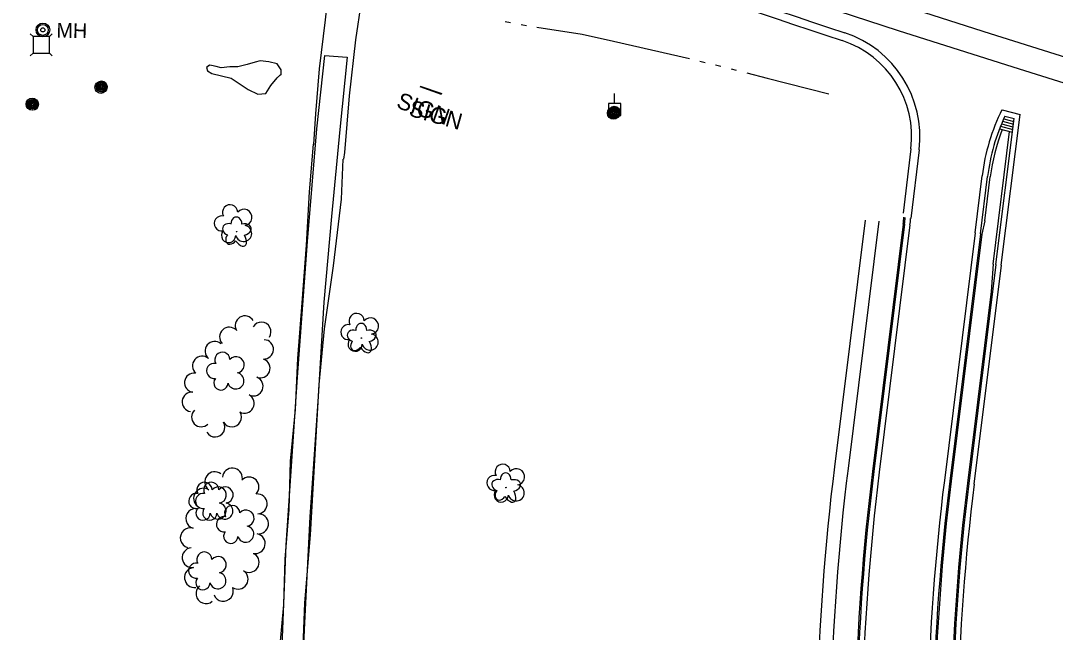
# Model space of a CAD drawing. Extents: x 588843 to 2552415, y 180129 to 269402.
# Drawn here: x 596189.9 to 596568.3, y 184162.7 to 184386.4 of the extents above; entities that cross this region are included whole.
import ezdxf

# ---------------------------------------------------------------- set-up
doc = ezdxf.new("R2010")
doc.units = 0
for name, color, linetype in [('C-ROAD-CURB-BACK-N-STH20-2', 7, 'Continuous'), ('C-ROAD-CURB-FACE-N-STH20-2', 7, 'Continuous'), ('C-ROAD-CURB-FLANGE-N-STH20-2', 7, 'Continuous'), ('Default', 7, 'Continuous'), ('E_DWY', 7, 'Continuous'), ('E_LAND_TreeLine_P', 7, 'Continuous'), ('E_LAND_Vegetation', 7, 'Continuous'), ('E_MISCPROP', 7, 'Continuous'), ('E_RDWY', 7, 'Continuous'), ('E_RDWY_Gravel', 7, 'Continuous'), ('E_SGN', 7, 'Continuous'), ('E_SGN_Text', 7, 'Continuous'), ('E_UTL_EPowerPole', 7, 'Continuous'), ('E_UTL_MH', 7, 'Continuous'), ('E_UTL_SAN', 7, 'Continuous'), ('E_WTR_P', 7, 'Continuous'), ('Level 14', 7, 'Continuous'), ('Level 17', 7, 'Continuous'), ('Level 18', 7, 'Continuous'), ('Level 19', 7, 'Continuous'), ('Level 21', 7, 'Continuous')]:
    doc.layers.add(name, color=color, linetype=linetype)

# ---------------------------------------------------------------- blocks, each defined once
blk = doc.blocks.new('POLE')
at = {"layer": 'Default'}
for radius in [4.46, 3.35, 2.23, 1.12]:
    blk.add_circle((0, 0), radius, dxfattribs=at)
blk = doc.blocks.new('SIGN')
at = {"layer": 'Default'}
blk.add_text('SIGN', height=12, dxfattribs=at).set_placement((-18.55, -6))
blk = doc.blocks.new('MH')
at = {"layer": 'E_UTL_MH'}
for radius in [5, 4, 1.5]:
    blk.add_circle((0, 0), radius, dxfattribs=at)
blk.add_text('MH', height=10.8, dxfattribs=at).set_placement((10, -5.4))
blk = doc.blocks.new('SIGN_3')
at = {"layer": 'E_SGN'}
blk.add_text('SIGN', height=39.37, dxfattribs=at).set_placement((-56.1, -19.7))
blk = doc.blocks.new('POLE_3')
at = {"layer": 'E_MISCPROP'}
for radius in [14.6, 11, 7.32, 3.66]:
    blk.add_circle((0, 0), radius, dxfattribs=at)
blk = doc.blocks.new('DTRE_4')
at = {"layer": 'E_LAND_Vegetation'}
blk.add_circle((-0.6, 0), 0.601, dxfattribs=at)
for centre, major_axis, ratio in [((-6.1, 17.5), (4.5, -16.3), 0.782863), ((13.3, 9), (-17.3, -9.6), 0.691916), ((-19.3, 0.5), (16.2, -0.4), 0.832022), ((-8.2, -17.2), (5.9, 15.9), 0.716896), ((11.6, -12.2), (-16.4, 15), 0.560249)]:
    blk.add_ellipse(centre, major_axis=major_axis, ratio=ratio, start_param=1.570796, end_param=4.712389, dxfattribs=at)

msp = doc.modelspace()

# ---------------------------------------------------------------- linework, layer by layer
at = {"layer": 'C-ROAD-CURB-BACK-N-STH20-2'}
for p, q in [((596545.58, 184297.28), (596551.62, 184345.8)), ((596547.91, 184346.8), (596552.59, 184345.54)), ((596542.52, 184313.17), (596544.53, 184329.3)), ((596542.52, 184313.17), (596541.45, 184308.29))]:
    msp.add_line(p, q, dxfattribs=at)
msp.add_arc((596615.97, 184320.41), 72, 158.7204, 172.9059, dxfattribs=at)
at = {"layer": 'C-ROAD-CURB-FACE-N-STH20-2'}
for p, q in [((596546.57, 184297.15), (596553.22, 184350.55)), ((596549.06, 184349.6), (596552.97, 184348.55)), ((596549.48, 184350.52), (596553.09, 184349.55)), ((596549.9, 184351.44), (596553.22, 184350.55)), ((596548.28, 184347.74), (596552.72, 184346.54)), ((596548.67, 184348.67), (596552.84, 184347.54)), ((596540.96, 184308.4), (596543.53, 184329.42))]:
    msp.add_line(p, q, dxfattribs=at)
msp.add_arc((596615.97, 184320.41), 73, 154.8409, 172.9059, dxfattribs=at)
at = {"layer": 'C-ROAD-CURB-FLANGE-N-STH20-2'}
for p, q in [((596548.82, 184353.81), (596555.42, 184352.03)), ((596548.56, 184296.91), (596555.42, 184352.03)), ((596539, 184308.83), (596541.55, 184329.67))]:
    msp.add_line(p, q, dxfattribs=at)
msp.add_arc((596615.97, 184320.41), 75, 153.5579, 172.9059, dxfattribs=at)
at = {"layer": 'E_DWY'}
for points in [[(596290.97, 184460.54), (596295.53, 184454.25), (596299.41, 184447.58), (596301.75, 184439.79), (596303.47, 184432.76), (596304.56, 184425.1), (596304.14, 184416.8), (596302.91, 184401.69), (596301.19, 184386.71), (596299.06, 184368.73), (596297.69, 184352.26), (596296.95, 184341.16)], [(596353.91, 184437.27), (596348.43, 184436.95), (596342.49, 184435.95), (596337.19, 184434.41), (596331.48, 184430.97), (596328.08, 184428.43), (596324.89, 184425.61), (596321.42, 184421.31), (596319.34, 184417.39), (596317.74, 184413.72), (596316.45, 184407.31), (596312.33, 184379.36), (596309.97, 184358.92), (596308.29, 184338.18), (596307.96, 184335.69)], [(596301.04, 184373.66), (596298.11, 184346.87), (596294.61, 184305.58), (596291.04, 184256.01), (596286.9, 184194.55), (596284.63, 184139.31), (596281.58, 184091.57), (596279.28, 184055.66)], [(596309.26, 184372.99), (596306.64, 184346.52), (596303.55, 184314.78), (596300.77, 184283.37), (596298.7, 184248.96), (596295.66, 184204.95), (596293.69, 184166.14), (596292.11, 184132), (596292.06, 184096.28), (596292.01, 184056.2)], [(596301.04, 184373.64), (596309.26, 184372.99)], [(596296.95, 184341.16), (596296.94, 184340.91)]]:
    msp.add_lwpolyline(points, dxfattribs=at)
at = {"layer": 'E_LAND_TreeLine_P'}
for centre, radius, start, end in [((596271.87, 184274.85), 3.54, 30.6326, 210.6326), ((596266.16, 184270.72), 3.54, 42.9001, 222.9001), ((596277.88, 184272.56), 3.54, 327.7743, 147.7743), ((596260.83, 184265.53), 3.54, 49.7198, 229.7198), ((596278.8, 184266.15), 3.54, 267.0712, 87.0712), ((596256.25, 184260.12), 3.54, 49.7198, 229.7198), ((596277.55, 184259.26), 3.54, 248.9694, 68.9694), ((596253.34, 184253.97), 3.54, 82.6946, 262.6946), ((596275, 184252.65), 3.54, 248.9694, 68.9694), ((596252.44, 184246.94), 3.54, 82.6946, 262.6946), ((596271.72, 184246.37), 3.54, 241.2564, 61.2564), ((596255.9, 184241.38), 3.54, 134.4189, 314.4189), ((596267.09, 184241.33), 3.54, 211.2849, 31.2849), ((596261.03, 184237.65), 3.54, 211.2849, 31.2849), ((596260.85, 184217.73), 3.66, 52.9133, 232.9133), ((596267.3, 184219.07), 3.66, 355.4737, 175.4737), ((596273.36, 184215.78), 3.66, 315.1092, 135.1092), ((596256.78, 184211.68), 3.66, 65.7368, 245.7368), ((596276.36, 184209.61), 3.66, 273.8176, 93.8176), ((596253.92, 184204.29), 3.66, 74.1638, 254.1638), ((596276.84, 184202.3), 3.66, 273.8176, 93.8176), ((596251.92, 184197.24), 3.66, 74.1638, 254.1638), ((596275.65, 184195.1), 3.66, 258.178, 78.178), ((596252.61, 184189.98), 3.66, 96.6673, 276.6673), ((596273.42, 184188.23), 3.66, 236.5512, 56.5512), ((596253.46, 184182.7), 3.66, 96.6673, 276.6673), ((596269.38, 184182.12), 3.66, 236.5512, 56.5512), ((596257.65, 184176.83), 3.66, 129.2885, 309.2885), ((596264, 184177.68), 3.66, 201.2807, 21.2807)]:
    msp.add_arc(centre, radius, start, end, dxfattribs=at)
at = {"layer": 'E_RDWY'}
for points in [[(595944.91, 184608.43), (595961.18, 184603.08), (595975.38, 184597.49), (596005.04, 184584.51), (596046.53, 184566.71), (596092.38, 184547.47), (596140.6, 184527.77), (596188.57, 184508.66), (596236, 184490.22), (596283.28, 184472.34), (596335.36, 184453.1), (596389, 184433.84), (596442.9, 184415.12), (596490.31, 184399.18), (596544.44, 184381.64), (596596.04, 184365.45), (596657.88, 184346.56), (596699.92, 184334.01), (596744.2, 184321.66), (596790.46, 184308.95), (596813.68, 184302.57)], [(596515.5, 184339.48), (596512.63, 184316.01)], [(596518.48, 184339.12), (596515.41, 184314.08)], [(596498.75, 184313.41), (596487.54, 184223.23)], [(596503.75, 184313.08), (596492.51, 184222.62)], [(596512.68, 184311.97), (596501.44, 184221.51)], [(596513.18, 184311.91), (596501.93, 184221.45)], [(596515.16, 184311.66), (596503.92, 184221.2)], [(596539, 184308.83), (596527.74, 184218.24)], [(596540.96, 184308.4), (596529.72, 184217.99)], [(596541.45, 184308.29), (596530.22, 184217.93)], [(596545.58, 184297.28), (596544.88, 184287.29), (596536.17, 184217.19)], [(596546.61, 184297.15), (596536.67, 184217.13)], [(596538.65, 184216.88), (596548.6, 184296.9)]]:
    msp.add_lwpolyline(points, dxfattribs=at)
for centre, radius, start, end in [((598307.84, 189884.49), 5794.62, 249.753018, 251.730667), ((598307.84, 189884.49), 5797.62, 249.75172, 251.730667), ((596478.78, 184343.98), 40, 353.0262, 71.7307), ((596478.78, 184343.98), 37, 353.0262, 71.7307), ((596455.62, 184319.06), 57.5, 352.9143, 355.4734), ((596455.62, 184319.06), 58, 352.9143, 355.4056), ((596455.62, 184319.06), 60, 352.9143, 355.1459), ((597340.98, 184117.15), 860, 172.91432, 184.56653), ((597340.98, 184117.15), 855, 172.91432, 184.56653), ((597340.98, 184117.15), 846, 172.91432, 184.56653), ((597340.98, 184117.15), 845.5, 172.91432, 184.56653), ((597340.98, 184117.15), 843.5, 172.91432, 184.56653), ((597340.98, 184117.15), 819.5, 172.91432, 184.56653), ((597340.98, 184117.15), 817.5, 172.91432, 184.56653), ((597340.98, 184117.15), 817, 172.91432, 184.56653), ((597340.98, 184117.15), 811, 172.91432, 184.56653), ((597340.98, 184117.15), 810.5, 172.91432, 184.56653), ((597340.98, 184117.15), 808.5, 172.91432, 184.56653)]:
    msp.add_arc(centre, radius, start, end, dxfattribs=at)
at = {"layer": 'E_RDWY_Gravel'}
msp.add_lwpolyline([(595950.7, 184598.98), (595988.96, 184582), (596020.07, 184568.3), (596058.18, 184552.5), (596097.71, 184535.89), (596142.07, 184517.59), (596181.54, 184501.83), (596221.92, 184486.01), (596263.36, 184470.62), (596301.66, 184456.22), (596341.33, 184441.54), (596379.47, 184427.71), (596421.23, 184413.06), (596466.73, 184397.35), (596510.79, 184382.78), (596555.12, 184368.75), (596596.32, 184355.82), (596643.98, 184341.47), (596696.01, 184326.08), (596743.17, 184312.91), (596792.52, 184299.02), (596809.86, 184294.62)], dxfattribs=at)
at = {"layer": 'E_SGN'}
msp.add_line((596335.84, 184362.27), (596343.69, 184359.52), dxfattribs=at)
msp.add_lwpolyline([(596343.98, 184359.58), (596336.14, 184362.36)], dxfattribs=at)
at = {"layer": 'E_UTL_EPowerPole'}
msp.add_line((596407.13, 184356.14), (596407.13, 184359.69), dxfattribs=at)
msp.add_lwpolyline([(596404.88, 184351.64), (596409.38, 184351.64), (596409.38, 184356.14), (596404.88, 184356.14)], close=True, dxfattribs=at)
msp.add_circle((596407.17, 184353.89), 0.291, dxfattribs=at)
at = {"layer": 'E_WTR_P'}
for points in [[(596367.12, 184386.07), (596369.05, 184385.7)], [(596372.91, 184384.95), (596373.59, 184384.82), (596374.84, 184384.62)], [(596378.72, 184384.03), (596395.28, 184381.47), (596406.71, 184378.87)], [(596406.71, 184378.87), (596413.63, 184377.3), (596434.47, 184372.54)], [(596438.29, 184371.62), (596440.2, 184371.14)], [(596444.01, 184370.18), (596445.91, 184369.69)], [(596449.72, 184368.73), (596451.62, 184368.25)], [(596455.43, 184367.29), (596462.91, 184365.4), (596485.47, 184359.62)]]:
    msp.add_lwpolyline(points, dxfattribs=at)
at = {"layer": 'Level 14'}
for centre, radius in [((596219.45, 184362.3), 2.02), ((596219.44, 184362.32), 1.52), ((596219.45, 184362.28), 1.01), ((596219.45, 184362.29), 0.502), ((596194.3, 184355.61), 2.02), ((596194.3, 184355.63), 1.52), ((596194.3, 184355.59), 1.01), ((596194.31, 184355.6), 0.502)]:
    msp.add_circle(centre, radius, dxfattribs=at)
at = {"layer": 'Level 17'}
for points in [[(596279.19, 184072.64), (596280.02, 184076.96), (596281.42, 184091.89), (596281.51, 184106.8), (596282.93, 184121.2), (596283.58, 184137.13), (596284.57, 184155.56), (596286.13, 184172.68), (596286.57, 184189.45), (596288.09, 184207.56), (596288.6, 184225.23), (596290.4, 184244.18), (596291.28, 184262.84), (596292.8, 184283.16), (596294.45, 184304.25), (596295.54, 184323.76), (596296.93, 184341.23)], [(596298.33, 184067.06), (596299.09, 184073.23), (596296.41, 184086.89), (596292.78, 184105.08), (596292.25, 184127.21), (596292.81, 184148.12), (596293.76, 184173.39), (596295.92, 184198.27), (596297.47, 184225.62), (596299.04, 184253.35), (596300.95, 184273.66), (596304.27, 184296.71), (596307.26, 184321.08), (596307.79, 184335.78)]]:
    msp.add_lwpolyline(points, dxfattribs=at)
at = {"layer": 'Level 18'}
for centre, radius, start, end in [((596266.46, 184316.29), 2.78, 1.3946, 209.1675), ((596271.5, 184314.43), 2.97, 278.4237, 139.6575), ((596263.46, 184312.21), 2.78, 78.0716, 279.0826), ((596271.39, 184308.58), 2.97, 196.0745, 79.0477), ((596265.92, 184307.81), 2.61, 140.7797, 358.7123), ((596312.74, 184276.54), 2.78, 1.3946, 209.1675), ((596317.79, 184274.68), 2.97, 278.4237, 139.6575), ((596309.74, 184272.46), 2.78, 78.0716, 279.0826), ((596317.68, 184268.82), 2.97, 196.0745, 79.0477), ((596312.21, 184268.06), 2.61, 140.7797, 358.7123), ((596263.64, 184262.35), 2.78, 1.3946, 209.1675), ((596268.68, 184260.49), 2.97, 278.4237, 139.6575), ((596260.64, 184258.27), 2.78, 78.0716, 279.0826), ((596263.1, 184253.87), 2.61, 140.7797, 358.7123), ((596268.57, 184254.64), 2.97, 196.0745, 79.0477), ((596366.19, 184221.37), 2.78, 1.3946, 209.1675), ((596371.23, 184219.51), 2.97, 278.4237, 139.6575), ((596257.1, 184214.75), 2.78, 1.3946, 209.1675), ((596259.58, 184214.75), 2.78, 1.3946, 209.1675), ((596363.19, 184217.29), 2.78, 78.0716, 279.0826), ((596254.1, 184210.67), 2.78, 78.0716, 279.0826), ((596256.58, 184210.67), 2.78, 78.0716, 279.0826), ((596262.14, 184212.89), 2.97, 278.4237, 139.6575), ((596264.62, 184212.89), 2.97, 278.4237, 139.6575), ((596365.65, 184212.89), 2.61, 140.7797, 358.7123), ((596371.12, 184213.66), 2.97, 196.0745, 79.0477), ((596262.03, 184207.04), 2.97, 196.0745, 79.0477), ((596264.51, 184207.04), 2.97, 196.0745, 79.0477), ((596256.56, 184206.27), 2.61, 140.7797, 358.7123), ((596259.04, 184206.28), 2.61, 140.7797, 358.7123), ((596267.23, 184206.28), 2.78, 1.3946, 209.1675), ((596272.27, 184204.42), 2.97, 278.4237, 139.6575), ((596264.23, 184202.2), 2.78, 78.0716, 279.0826), ((596266.69, 184197.8), 2.61, 140.7797, 358.7123), ((596272.16, 184198.56), 2.97, 196.0745, 79.0477), ((596257.06, 184189.26), 2.78, 1.3946, 209.1675), ((596262.1, 184187.41), 2.97, 278.4237, 139.6575), ((596254.06, 184185.19), 2.78, 78.0716, 279.0826), ((596261.99, 184181.55), 2.97, 196.0745, 79.0477), ((596256.52, 184180.79), 2.61, 140.7797, 358.7123)]:
    msp.add_arc(centre, radius, start, end, dxfattribs=at)
at = {"layer": 'Level 19'}
for points in [[(596285.13, 184368.42), (596283.69, 184370.61), (596280.62, 184371.27), (596277.43, 184371.68), (596275.6, 184371.25), (596272.65, 184370.38), (596269.34, 184369.54), (596266.37, 184369.49), (596263.18, 184369.18), (596261.4, 184369.64), (596259.72, 184370), (596258.97, 184370.07), (596257.89, 184369.29)], [(596257.89, 184369.29), (596258.2, 184367.99), (596259.83, 184367.02), (596266.84, 184365.33), (596273.02, 184361.24), (596276.61, 184359.52), (596279.48, 184359.75), (596281.38, 184362.68), (596283.74, 184365.43), (596285.15, 184366.86), (596285.13, 184368.42)], [(596257.89, 184369.29), (596258.2, 184367.99), (596259.83, 184367.02), (596266.84, 184365.33), (596273.02, 184361.24), (596276.61, 184359.52), (596279.48, 184359.75), (596281.38, 184362.68), (596281.9, 184363.29)], [(596285.13, 184368.42), (596283.69, 184370.61), (596280.62, 184371.27), (596277.43, 184371.68), (596275.6, 184371.25), (596272.65, 184370.38), (596269.34, 184369.54), (596266.37, 184369.49), (596263.18, 184369.18), (596261.4, 184369.64), (596259.72, 184370), (596258.97, 184370.07), (596258.02, 184369.39)], [(596284.56, 184366.27), (596285.15, 184366.86), (596285.13, 184368.03)]]:
    msp.add_lwpolyline(points, dxfattribs=at)
at = {"layer": 'Level 21'}
for p, q in [((596194.38, 184380.55), (596193.32, 184381.61)), ((596200.38, 184380.55), (596201.44, 184381.61)), ((596193.32, 184373.49), (596194.38, 184374.55)), ((596201.44, 184373.49), (596200.38, 184374.55))]:
    msp.add_line(p, q, dxfattribs=at)
msp.add_lwpolyline([(596194.38, 184374.55), (596200.38, 184374.55), (596200.38, 184380.55), (596194.38, 184380.55)], close=True, dxfattribs=at)

# ---------------------------------------------------------------- block references
at = {"layer": 'E_LAND_Vegetation', "xscale": 0.1524003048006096, "yscale": 0.15240030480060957, "rotation": -15.836204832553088}
for p in [(596268.92, 184309.17), (596314.59, 184270.25), (596367.43, 184215.58)]:
    msp.add_blockref('DTRE_4', p, dxfattribs=at)
at = {"layer": 'E_MISCPROP'}
for name, p, xscale, yscale, rotation in [('POLE_3', (596219.23, 184362), 0.1524003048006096, 0.15240030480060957, -15.836204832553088), ('POLE_3', (596194.1, 184355.83), 0.1524003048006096, 0.15240030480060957, -15.836204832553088), ('POLE_3', (596406.73, 184352.55), 0.1524003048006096, 0.15240030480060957, -15.836204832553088), ('POLE', (596407.01, 184352.82), 0.4999999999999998, 0.49999999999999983, 158.45495281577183)]:
    msp.add_blockref(name, p, dxfattribs=dict(at, xscale=xscale, yscale=yscale, rotation=rotation))
at = {"layer": 'E_SGN_Text'}
for name, p, xscale, yscale, rotation in [('SIGN', (596336.7, 184354.38), 0.5, 0.5, -19.58850729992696), ('SIGN_3', (596340.52, 184352.26), 0.1524003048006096, 0.15240030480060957, -15.836204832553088)]:
    msp.add_blockref(name, p, dxfattribs=dict(at, xscale=xscale, yscale=yscale, rotation=rotation))
at = {"layer": 'E_UTL_SAN', "xscale": 0.500001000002, "yscale": 0.5000010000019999, "rotation": -1.2027594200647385}
msp.add_blockref('MH', (596197.97, 184383.01), dxfattribs=at)

doc.saveas('drawing.dxf')
